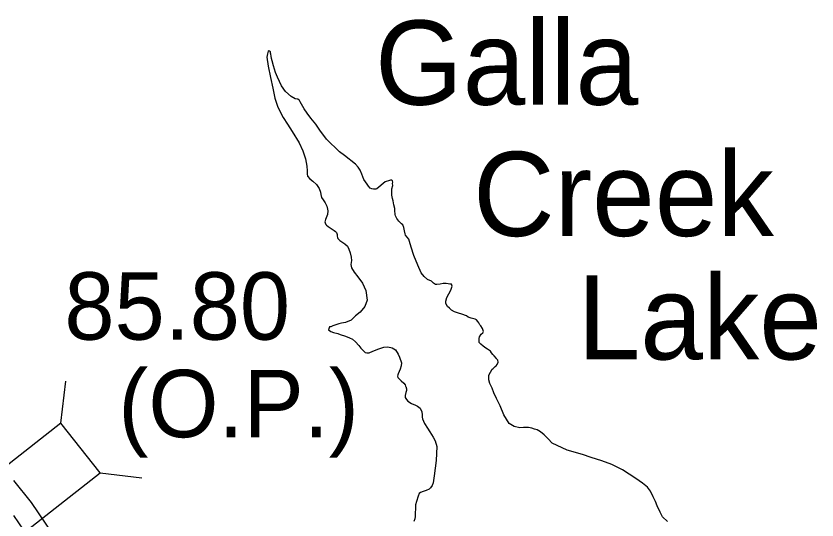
# Model space of a CAD drawing. Extents: x -83719 to 153526, y -11835 to 11446.
# Drawn here: x -1635.6 to -1468.4, y 1128.5 to 1233.8 of the extents above; entities that cross this region are included whole.
import ezdxf

# ---------------------------------------------------------------- set-up
doc = ezdxf.new("R2010")
doc.units = 0
for name, color, linetype in [('Level 19', 7, 'Continuous'), ('Level 20', 7, 'Continuous'), ('Level 58', 7, 'Continuous'), ('Level 9', 7, 'Continuous')]:
    doc.layers.add(name, color=color, linetype=linetype)

msp = doc.modelspace()

# ---------------------------------------------------------------- linework, layer by layer
at = {"layer": 'Level 19'}
for points in [[(-1557.79, 1077.69), (-1561.91, 1080), (-1566.66, 1082.77), (-1570.07, 1084.7), (-1574.52, 1086.71), (-1579.21, 1088.68), (-1585.13, 1090.87), (-1589.9, 1092.41), (-1594.48, 1094.12), (-1600, 1096.37), (-1603.96, 1098.27), (-1607.23, 1100.13), (-1610.99, 1103.17), (-1614.57, 1106.36), (-1617.69, 1109.47), (-1622.43, 1114.84), (-1625.72, 1120.42), (-1627.83, 1125.51), (-1632.38, 1132.16), (-1636.03, 1136.79)], [(-1559.99, 1073.68), (-1564.18, 1076.02), (-1568.94, 1078.79), (-1572.15, 1080.61), (-1576.35, 1082.51), (-1580.9, 1084.41), (-1586.63, 1086.54), (-1591.41, 1088.08), (-1596.15, 1089.85), (-1601.85, 1092.18), (-1606.08, 1094.2), (-1609.83, 1096.33), (-1613.96, 1099.68), (-1617.72, 1103.03), (-1621.03, 1106.33), (-1626.16, 1112.14), (-1629.83, 1118.37), (-1631.88, 1123.31), (-1636.08, 1129.44)]]:
    msp.add_lwpolyline(points, dxfattribs=at)
at = {"layer": 'Level 20'}
for p, q in [((-1626.23, 1148.76), (-1625.19, 1157.5)), ((-1618.06, 1138.39), (-1609.33, 1137.34))]:
    msp.add_line(p, q, dxfattribs=at)
msp.add_lwpolyline([(-1626.23, 1148.76), (-1657.35, 1124.27), (-1649.18, 1113.9), (-1618.06, 1138.39)], close=True, dxfattribs=at)
at = {"layer": 'Level 9'}
for points in [[(-1556.96, 1198.34), (-1557, 1198.78), (-1556.94, 1199.08), (-1556.97, 1199.34), (-1557.18, 1199.48), (-1557.44, 1199.51), (-1557.61, 1199.44), (-1558.54, 1199.12), (-1560.25, 1197.67), (-1560.48, 1197.6), (-1560.94, 1197.59), (-1561.31, 1197.68), (-1561.68, 1197.85), (-1562.02, 1198.21), (-1562.29, 1198.67), (-1562.97, 1199.63), (-1563.38, 1200.73), (-1563.76, 1201.59), (-1564.13, 1202.22), (-1564.71, 1202.85), (-1566.99, 1204.62), (-1568.03, 1205.41), (-1570.8, 1208.04), (-1572.19, 1209.93), (-1573.03, 1211.18), (-1574.08, 1212.47), (-1574.83, 1213.46), (-1575.47, 1214.42), (-1576.02, 1215.35), (-1576.25, 1215.85), (-1576.39, 1216.15), (-1576.79, 1216.38), (-1577.29, 1216.5), (-1578.17, 1216.93), (-1579.34, 1217.98), (-1580.16, 1219.17), (-1580.98, 1220.99), (-1581.39, 1221.99), (-1581.84, 1223.35), (-1582.12, 1224.42), (-1582.23, 1224.88), (-1582.33, 1225.38), (-1582.41, 1225.82), (-1582.44, 1226.05), (-1582.45, 1226.28), (-1582.68, 1226.45), (-1582.85, 1226.51), (-1582.98, 1226.44), (-1583.11, 1225.91), (-1583.2, 1225.17), (-1582.94, 1223.27), (-1582.48, 1220.94), (-1581.98, 1218.71), (-1581.56, 1216.61), (-1580.97, 1214.95), (-1580.56, 1214.02), (-1579.81, 1212.56), (-1578.92, 1211.17), (-1577.91, 1209.65), (-1576.51, 1207.3), (-1575.72, 1205.61), (-1575.14, 1203.91), (-1574.85, 1202.38), (-1574.8, 1201.45), (-1574.8, 1200.81), (-1574.72, 1200.31), (-1574.28, 1199.78), (-1573.65, 1199.26), (-1572.84, 1198.6), (-1572.3, 1197.77), (-1572.05, 1196.98), (-1571.98, 1196.48), (-1571.84, 1195.88), (-1571.5, 1195.35), (-1571.06, 1194.75), (-1570.72, 1194.09), (-1570.54, 1193.46), (-1570.5, 1193.06), (-1570.59, 1192.29), (-1570.95, 1191.28), (-1571.08, 1190.98), (-1571.11, 1190.78), (-1571.07, 1190.55), (-1570.93, 1190.25), (-1570.77, 1190.08), (-1570.4, 1189.82), (-1569.79, 1189.39), (-1569.19, 1189), (-1568.88, 1188.77), (-1568.72, 1188.54), (-1568.65, 1188.37), (-1568.58, 1188.11), (-1568.57, 1187.81), (-1568.5, 1187.54), (-1568.4, 1187.31), (-1567.96, 1186.91), (-1566.95, 1186.19), (-1566.42, 1185.67), (-1566.08, 1185.07), (-1565.8, 1184.31), (-1565.62, 1183.41)], [(-1527.92, 1147.68), (-1528.59, 1147.81), (-1529.62, 1147.83), (-1530.42, 1147.78), (-1531.56, 1148.07), (-1532.63, 1148.65), (-1533.72, 1150.44), (-1534.54, 1152.37), (-1535.29, 1153.89), (-1535.81, 1155.09), (-1536.22, 1156.05), (-1536.66, 1157.01), (-1536.87, 1157.75), (-1536.85, 1158.78), (-1536.56, 1159.39), (-1536.2, 1159.99), (-1535.97, 1160.16), (-1535.74, 1160.36), (-1535.54, 1160.57), (-1535.35, 1160.74), (-1535.15, 1161.01), (-1535.05, 1161.14), (-1534.96, 1161.48), (-1534.99, 1161.88), (-1535.2, 1162.11), (-1535.3, 1162.21), (-1535.8, 1162.8), (-1536.07, 1163.1), (-1536.31, 1163.43), (-1536.55, 1163.76), (-1537.15, 1164.18), (-1537.52, 1164.38), (-1538.09, 1164.84), (-1538.56, 1165.23), (-1538.87, 1165.56), (-1538.91, 1165.9), (-1538.88, 1166.4), (-1538.82, 1166.77), (-1538.46, 1167.31), (-1538.16, 1167.58), (-1538.03, 1167.91), (-1538.17, 1168.54), (-1538.55, 1169.04), (-1538.75, 1169.27), (-1538.99, 1169.67), (-1539.16, 1169.97), (-1539.46, 1170.3), (-1539.76, 1170.49), (-1540.56, 1170.68), (-1541.17, 1170.88), (-1541.54, 1171.17), (-1542.54, 1171.53), (-1543.21, 1171.68), (-1544.04, 1171.97), (-1544.65, 1172.37), (-1545.08, 1172.73), (-1545.49, 1173.12), (-1545.86, 1173.75), (-1545.87, 1174.22), (-1545.68, 1174.96), (-1544.83, 1176.5), (-1544.67, 1176.91), (-1544.54, 1177.37), (-1544.68, 1177.74), (-1545.05, 1177.8), (-1545.38, 1177.86), (-1545.78, 1177.89), (-1546.45, 1177.88), (-1547.05, 1177.74), (-1547.74, 1177.67), (-1548.01, 1177.73), (-1548.45, 1177.99), (-1548.82, 1178.39), (-1549.72, 1178.71), (-1550.39, 1179.4), (-1551, 1180.16), (-1551.69, 1181.75), (-1552.51, 1183.75), (-1553.07, 1185.51), (-1553.48, 1186.67), (-1553.59, 1187.14), (-1554.3, 1188.03), (-1554.37, 1188.3), (-1554.51, 1188.93), (-1554.62, 1189.59), (-1554.83, 1190.13), (-1555.09, 1190.39), (-1555.26, 1190.49), (-1555.67, 1190.92), (-1556.11, 1191.48), (-1556.35, 1192.01), (-1556.42, 1192.34), (-1556.53, 1193.14), (-1556.53, 1193.54), (-1556.71, 1194.37), (-1556.89, 1195.14), (-1556.99, 1195.67), (-1557.1, 1196.34), (-1557.15, 1197.17), (-1557.12, 1197.67), (-1556.96, 1198.34)], [(-1565.62, 1183.41), (-1565.58, 1182.74), (-1565.67, 1181.87), (-1565.53, 1181.2), (-1564.98, 1180.24), (-1564.2, 1179.32), (-1563.29, 1178), (-1562.57, 1176.47), (-1562.28, 1174.44), (-1562.76, 1173.09), (-1563.78, 1171.91), (-1564.7, 1171.17), (-1565.65, 1170.25), (-1566.78, 1169.74), (-1567.64, 1169.59), (-1568.17, 1169.45), (-1569, 1169.21), (-1569.46, 1169.07), (-1569.89, 1168.86), (-1570.16, 1168.82), (-1570.35, 1168.25), (-1569.85, 1167.86), (-1569.28, 1167.67), (-1568.44, 1167.44), (-1567.91, 1167.28), (-1566.81, 1166.9), (-1565.94, 1166.54), (-1565.33, 1166.25), (-1564.69, 1165.72), (-1564.05, 1164.97), (-1563.58, 1164.37), (-1563.01, 1163.74), (-1562.67, 1163.51), (-1562.37, 1163.45), (-1561.9, 1163.42), (-1561.11, 1163.74), (-1559.85, 1164.25), (-1558.82, 1164.6), (-1557.99, 1164.68), (-1557.06, 1164.49), (-1556.39, 1164.03), (-1555.81, 1163.17), (-1555.54, 1162.51), (-1555.15, 1161.31), (-1555.18, 1160.74), (-1555.37, 1160.01), (-1555.6, 1159.53), (-1555.82, 1159.03), (-1555.89, 1158.83), (-1555.92, 1158.56), (-1555.85, 1158.3), (-1555.54, 1157.9), (-1555.17, 1157.6), (-1554.63, 1157.11), (-1554.36, 1156.71), (-1554.26, 1156.48), (-1554.19, 1156.38), (-1554.05, 1155.88), (-1554.05, 1155.58), (-1554.18, 1155.11), (-1554.33, 1154.54), (-1554.36, 1154.31), (-1554.33, 1154.11), (-1554.06, 1153.65), (-1553.82, 1153.35), (-1553.02, 1152.86), (-1552.21, 1152.5), (-1551.78, 1152.27), (-1551.2, 1151.85), (-1550.86, 1151.08), (-1550.82, 1150.48), (-1550.82, 1150.02), (-1550.74, 1149.62), (-1550.3, 1148.65), (-1549.72, 1147.69), (-1549.18, 1146.9), (-1548.5, 1145.84), (-1548.06, 1145.05), (-1547.77, 1143.88), (-1547.87, 1140.97), (-1548.29, 1137.7), (-1548.48, 1136.29), (-1548.73, 1135.69), (-1549.09, 1135.25), (-1549.36, 1134.98), (-1549.95, 1134.7), (-1550.62, 1134.46), (-1551.18, 1134.22), (-1551.41, 1134.05), (-1551.67, 1133.51), (-1551.99, 1132.37), (-1552.18, 1131.67), (-1552.2, 1130.97), (-1552.25, 1129.9), (-1552.28, 1129.27), (-1552.34, 1128.76), (-1552.56, 1128.16)], [(-1499.58, 1128.16), (-1500.6, 1129.15), (-1501.14, 1130.17), (-1501.72, 1131.5), (-1502.1, 1132.4), (-1502.58, 1133.36), (-1503.13, 1134.55), (-1503.77, 1135.38), (-1504.78, 1136.23), (-1506.16, 1137.15), (-1508.98, 1138.98), (-1511.22, 1140.09), (-1513.29, 1140.9), (-1515.53, 1141.57), (-1517.3, 1142.18), (-1520.54, 1143.07), (-1523.66, 1144.53), (-1524.47, 1145.46), (-1525.31, 1146.28), (-1526.12, 1146.94), (-1526.79, 1147.36), (-1527.35, 1147.49), (-1527.92, 1147.68)]]:
    msp.add_lwpolyline(points, dxfattribs=at)

# ---------------------------------------------------------------- texts
at = {"layer": 'Level 58'}
for s, p in [('85.80', (-1625.5, 1166.17)), ('(O.P.)', (-1614.23, 1145.79))]:
    msp.add_text(s, height=14.08, dxfattribs=at).set_placement(p)
at = {"layer": 'Level 9'}
for s, p in [('Galla', (-1560.63, 1215.24)), ('Creek', (-1540.16, 1187.82)), ('Lake', (-1518.36, 1162.04))]:
    msp.add_text(s, height=17.6, dxfattribs=at).set_placement(p)

doc.saveas('drawing.dxf')
